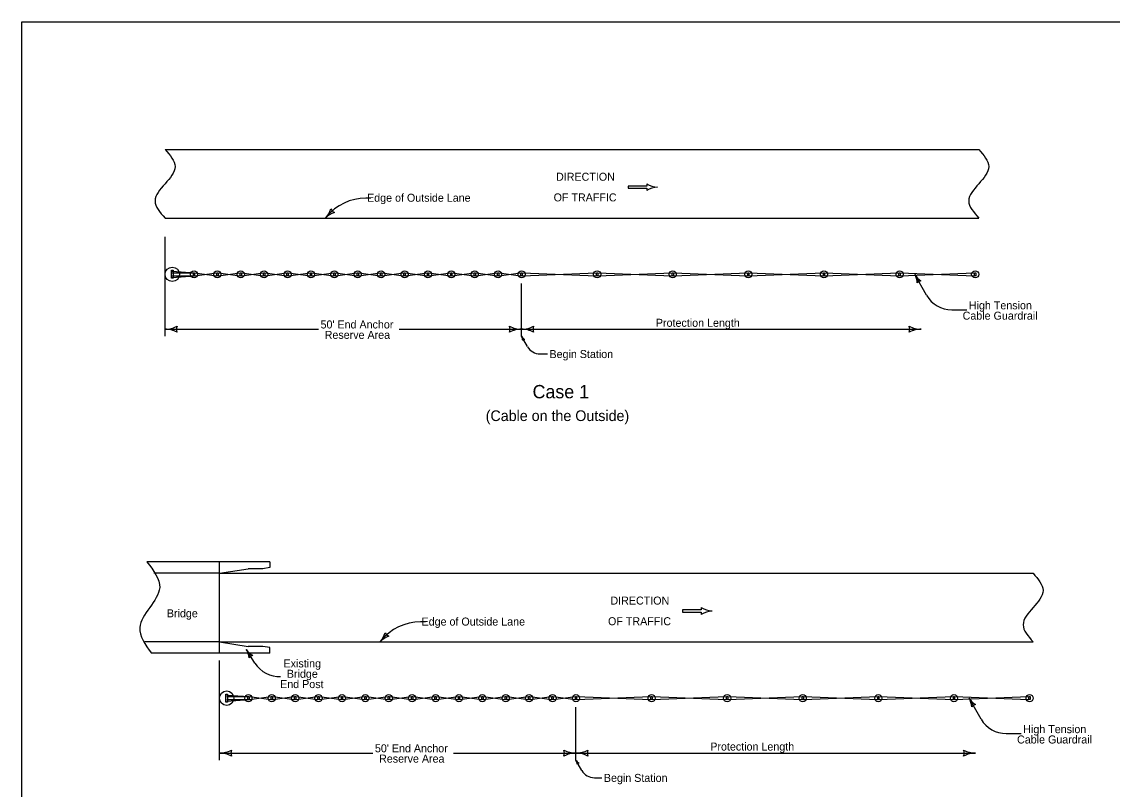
# Model space of a CAD drawing. Extents: x 10133 to 81668, y 7924 to 11018.
# Drawn here: x 20933 to 22568, y 8793 to 9944 of the extents above; entities that cross this region are included whole.
import ezdxf

# ---------------------------------------------------------------- set-up
doc = ezdxf.new("R2010")
doc.units = 0
for name, color, linetype in [('Default', 7, 'Continuous'), ('dsnCellElements', 7, 'Continuous'), ('DsnShtRevisedText', 7, 'Continuous'), ('dsnStdDimension', 7, 'Continuous'), ('Level 8', 7, 'Continuous'), ('SheetBorder', 7, 'Continuous')]:
    doc.layers.add(name, color=color, linetype=linetype)

msp = doc.modelspace()

# ---------------------------------------------------------------- linework, layer by layer
at = {"layer": 'Default'}
for p, q in [((21229, 9133.8), (21120.1, 9133.8)), ((21229, 8996.7), (21229, 9133.8)), ((21229, 9116.7), (21130.7, 9116.7)), ((21229, 9013.8), (21117.2, 9013.8)), ((21229, 8996.7), (21127, 8996.7))]:
    msp.add_line(p, q, dxfattribs=at)
msp.add_spline([(21120.1, 9133.8), (21139.3, 9095.3), (21124.3, 9065.3), (21109.3, 9035.3), (21127, 8996.7)], degree=3, dxfattribs=at)
at = {"layer": 'dsnCellElements'}
for p, q in [((21158.2, 9569.8), (21191.7, 9567.5)), ((21158.2, 9567.5), (21189.8, 9567.5)), ((21158.2, 9563), (21189.8, 9563)), ((21158.2, 9560.6), (21191.7, 9563)), ((21191.7, 9567.5), (21224.9, 9563)), ((21191.7, 9563), (21224.9, 9567.5)), ((21226.8, 9567.5), (21260, 9563)), ((21226.8, 9563), (21260, 9567.5)), ((21261.9, 9567.5), (21295.1, 9563)), ((21261.9, 9563), (21295.1, 9567.5)), ((21297, 9567.5), (21330.2, 9563)), ((21297, 9563), (21330.2, 9567.5)), ((21332.1, 9567.5), (21365.3, 9563)), ((21332.1, 9563), (21365.3, 9567.5)), ((21367.2, 9567.5), (21400.4, 9563)), ((21367.2, 9563), (21400.4, 9567.5)), ((21402.3, 9563), (21435.5, 9567.5)), ((21402.3, 9567.5), (21435.5, 9563)), ((21437.3, 9567.5), (21470.6, 9563)), ((21437.3, 9563), (21470.6, 9567.5)), ((21472.5, 9567.5), (21505.6, 9563)), ((21472.5, 9563), (21505.6, 9567.5)), ((21507.5, 9567.5), (21540.8, 9563)), ((21507.5, 9563), (21540.8, 9567.5)), ((21542.7, 9567.5), (21575.8, 9563)), ((21542.7, 9563), (21575.8, 9567.5)), ((21577.7, 9567.5), (21611, 9563)), ((21577.7, 9563), (21611, 9567.5)), ((21612.8, 9567.5), (21646, 9563)), ((21612.8, 9563), (21646, 9567.5)), ((21647.9, 9567.5), (21681.1, 9563)), ((21647.9, 9563), (21681.1, 9567.5)), ((21683, 9567.5), (21794.5, 9563)), ((21683, 9563), (21794.5, 9567.5)), ((21796.4, 9567.5), (21907.9, 9563)), ((21796.4, 9563), (21907.9, 9567.5)), ((21909.8, 9567.5), (22021.3, 9563)), ((21909.8, 9563), (22021.3, 9567.5)), ((22023.2, 9567.5), (22134.8, 9563)), ((22023.2, 9563), (22134.8, 9567.5)), ((22136.6, 9567.5), (22248.2, 9563)), ((22136.6, 9563), (22248.2, 9567.5)), ((22250, 9567.5), (22361.6, 9563)), ((22250, 9563), (22361.6, 9567.5)), ((21304.6, 9133.8), (21229, 9133.8)), ((21304.6, 9133.8), (21304.6, 9125.3)), ((21229, 9116.7), (21272.2, 9123.5)), ((21293.8, 9123.5), (21272.2, 9123.5)), ((21304.6, 9125.3), (21293.8, 9123.5)), ((21229, 8996.7), (21229, 9013.8)), ((21229, 9013.8), (21272.2, 9007.1)), ((21304.6, 8996.7), (21229, 8996.7)), ((21293.8, 9007.1), (21272.2, 9007.1)), ((21304.6, 9005.3), (21293.8, 9007.1)), ((21304.6, 8996.7), (21304.6, 9005.3)), ((21239.8, 8934.1), (21273.3, 8931.7)), ((21239.8, 8931.7), (21271.5, 8931.7)), ((21273.3, 8931.7), (21306.5, 8927.2)), ((21273.3, 8927.2), (21306.5, 8931.7)), ((21308.4, 8931.7), (21341.6, 8927.2)), ((21308.4, 8927.2), (21341.6, 8931.7)), ((21343.5, 8931.7), (21376.7, 8927.2)), ((21343.5, 8927.2), (21376.7, 8931.7)), ((21378.6, 8931.7), (21411.8, 8927.2)), ((21378.6, 8927.2), (21411.8, 8931.7)), ((21413.7, 8931.7), (21446.9, 8927.2)), ((21413.7, 8927.2), (21446.9, 8931.7)), ((21448.8, 8931.7), (21482, 8927.2)), ((21448.8, 8927.2), (21482, 8931.7)), ((21483.9, 8927.2), (21517.1, 8931.7)), ((21483.9, 8931.7), (21517.1, 8927.2)), ((21519, 8931.7), (21552.2, 8927.2)), ((21519, 8927.2), (21552.2, 8931.7)), ((21554.1, 8931.7), (21587.3, 8927.2)), ((21554.1, 8927.2), (21587.3, 8931.7)), ((21589.1, 8931.7), (21622.4, 8927.2)), ((21589.1, 8927.2), (21622.4, 8931.7)), ((21624.3, 8931.7), (21657.4, 8927.2)), ((21624.3, 8927.2), (21657.4, 8931.7)), ((21659.3, 8931.7), (21692.6, 8927.2)), ((21659.3, 8927.2), (21692.6, 8931.7)), ((21694.5, 8931.7), (21727.6, 8927.2)), ((21694.5, 8927.2), (21727.6, 8931.7)), ((21729.5, 8931.7), (21762.8, 8927.2)), ((21729.5, 8927.2), (21762.8, 8931.7)), ((21764.6, 8931.7), (21876.2, 8927.2)), ((21764.6, 8927.2), (21876.2, 8931.7)), ((21878, 8931.7), (21989.6, 8927.2)), ((21878, 8927.2), (21989.6, 8931.7)), ((21991.4, 8931.7), (22103, 8927.2)), ((21991.4, 8927.2), (22103, 8931.7)), ((22104.8, 8931.7), (22216.4, 8927.2)), ((22104.8, 8927.2), (22216.4, 8931.7)), ((22218.2, 8931.7), (22329.8, 8927.2)), ((22218.2, 8927.2), (22329.8, 8931.7)), ((22331.6, 8931.7), (22443.2, 8927.2)), ((22331.6, 8927.2), (22443.2, 8931.7)), ((21239.8, 8927.2), (21271.5, 8927.2)), ((21239.8, 8924.8), (21273.3, 8927.2))]:
    msp.add_line(p, q, dxfattribs=at)
for points in [[(21157, 9559.2), (21157, 9571.2), (21159.4, 9571.2), (21159.4, 9559.2)], [(21189.8, 9563), (21189.8, 9567.5), (21191.7, 9567.5), (21191.7, 9563)], [(21224.9, 9563), (21224.9, 9567.5), (21226.8, 9567.5), (21226.8, 9563)], [(21260, 9563), (21260, 9567.5), (21261.9, 9567.5), (21261.9, 9563)], [(21295.1, 9563), (21295.1, 9567.5), (21297, 9567.5), (21297, 9563)], [(21330.2, 9563), (21330.2, 9567.5), (21332.1, 9567.5), (21332.1, 9563)], [(21365.3, 9563), (21365.3, 9567.5), (21367.2, 9567.5), (21367.2, 9563)], [(21400.4, 9563), (21400.4, 9567.5), (21402.3, 9567.5), (21402.3, 9563)], [(21435.5, 9563), (21435.5, 9567.5), (21437.3, 9567.5), (21437.3, 9563)], [(21470.6, 9563), (21470.6, 9567.5), (21472.5, 9567.5), (21472.5, 9563)], [(21505.6, 9563), (21505.6, 9567.5), (21507.5, 9567.5), (21507.5, 9563)], [(21540.8, 9563), (21540.8, 9567.5), (21542.7, 9567.5), (21542.7, 9563)], [(21575.8, 9563), (21575.8, 9567.5), (21577.7, 9567.5), (21577.7, 9563)], [(21611, 9563), (21611, 9567.5), (21612.8, 9567.5), (21612.8, 9563)], [(21646, 9563), (21646, 9567.5), (21647.9, 9567.5), (21647.9, 9563)], [(21681.1, 9563), (21681.1, 9567.5), (21683, 9567.5), (21683, 9563)], [(21681.1, 9563), (21681.1, 9567.5), (21683, 9567.5), (21683, 9563)], [(21794.5, 9563), (21794.5, 9567.5), (21796.4, 9567.5), (21796.4, 9563)], [(21794.5, 9563), (21794.5, 9567.5), (21796.4, 9567.5), (21796.4, 9563)], [(21907.9, 9563), (21907.9, 9567.5), (21909.8, 9567.5), (21909.8, 9563)], [(21907.9, 9563), (21907.9, 9567.5), (21909.8, 9567.5), (21909.8, 9563)], [(22021.3, 9563), (22021.3, 9567.5), (22023.2, 9567.5), (22023.2, 9563)], [(22021.3, 9563), (22021.3, 9567.5), (22023.2, 9567.5), (22023.2, 9563)], [(22134.8, 9563), (22134.8, 9567.5), (22136.6, 9567.5), (22136.6, 9563)], [(22134.8, 9563), (22134.8, 9567.5), (22136.6, 9567.5), (22136.6, 9563)], [(22248.2, 9563), (22248.2, 9567.5), (22250, 9567.5), (22250, 9563)], [(22248.2, 9563), (22248.2, 9567.5), (22250, 9567.5), (22250, 9563)], [(22361.6, 9563), (22361.6, 9567.5), (22363.4, 9567.5), (22363.4, 9563)], [(21238.6, 8923.4), (21238.6, 8935.4), (21241, 8935.4), (21241, 8923.4)], [(21271.4, 8927.2), (21271.4, 8931.7), (21273.3, 8931.7), (21273.3, 8927.2)], [(21306.5, 8927.2), (21306.5, 8931.7), (21308.4, 8931.7), (21308.4, 8927.2)], [(21341.7, 8927.2), (21341.7, 8931.7), (21343.5, 8931.7), (21343.5, 8927.2)], [(21376.7, 8927.2), (21376.7, 8931.7), (21378.6, 8931.7), (21378.6, 8927.2)], [(21411.9, 8927.2), (21411.9, 8931.7), (21413.7, 8931.7), (21413.7, 8927.2)], [(21446.9, 8927.2), (21446.9, 8931.7), (21448.8, 8931.7), (21448.8, 8927.2)], [(21482, 8927.2), (21482, 8931.7), (21483.9, 8931.7), (21483.9, 8927.2)], [(21517.1, 8927.2), (21517.1, 8931.7), (21519, 8931.7), (21519, 8927.2)], [(21552.2, 8927.2), (21552.2, 8931.7), (21554.1, 8931.7), (21554.1, 8927.2)], [(21587.3, 8927.2), (21587.3, 8931.7), (21589.1, 8931.7), (21589.1, 8927.2)], [(21622.4, 8927.2), (21622.4, 8931.7), (21624.3, 8931.7), (21624.3, 8927.2)], [(21657.4, 8927.2), (21657.4, 8931.7), (21659.3, 8931.7), (21659.3, 8927.2)], [(21692.6, 8927.2), (21692.6, 8931.7), (21694.5, 8931.7), (21694.5, 8927.2)], [(21727.6, 8927.2), (21727.6, 8931.7), (21729.5, 8931.7), (21729.5, 8927.2)], [(21762.8, 8927.2), (21762.8, 8931.7), (21764.6, 8931.7), (21764.6, 8927.2)], [(21762.8, 8927.2), (21762.8, 8931.7), (21764.6, 8931.7), (21764.6, 8927.2)], [(21876.2, 8927.2), (21876.2, 8931.7), (21878, 8931.7), (21878, 8927.2)], [(21876.2, 8927.2), (21876.2, 8931.7), (21878, 8931.7), (21878, 8927.2)], [(21989.6, 8927.2), (21989.6, 8931.7), (21991.4, 8931.7), (21991.4, 8927.2)], [(21989.6, 8927.2), (21989.6, 8931.7), (21991.4, 8931.7), (21991.4, 8927.2)], [(22103, 8927.2), (22103, 8931.7), (22104.8, 8931.7), (22104.8, 8927.2)], [(22103, 8927.2), (22103, 8931.7), (22104.8, 8931.7), (22104.8, 8927.2)], [(22216.4, 8927.2), (22216.4, 8931.7), (22218.2, 8931.7), (22218.2, 8927.2)], [(22216.4, 8927.2), (22216.4, 8931.7), (22218.2, 8931.7), (22218.2, 8927.2)], [(22329.8, 8927.2), (22329.8, 8931.7), (22331.6, 8931.7), (22331.6, 8927.2)], [(22329.8, 8927.2), (22329.8, 8931.7), (22331.6, 8931.7), (22331.6, 8927.2)], [(22443.2, 8927.2), (22443.2, 8931.7), (22445, 8931.7), (22445, 8927.2)]]:
    msp.add_lwpolyline(points, close=True, dxfattribs=at)
for centre, radius in [((21158.2, 9565.2), 10.8), ((21190.8, 9565.2), 5.32), ((21225.8, 9565.2), 5.32), ((21261, 9565.2), 5.32), ((21296, 9565.2), 5.32), ((21331.2, 9565.2), 5.32), ((21366.2, 9565.2), 5.32), ((21401.4, 9565.2), 5.32), ((21436.4, 9565.2), 5.32), ((21471.5, 9565.2), 5.32), ((21506.6, 9565.2), 5.32), ((21541.7, 9565.2), 5.32), ((21576.8, 9565.2), 5.32), ((21611.9, 9565.2), 5.32), ((21646.9, 9565.2), 5.32), ((21682.1, 9565.2), 5.32), ((21682.1, 9565.2), 5.32), ((21795.5, 9565.2), 5.32), ((21795.5, 9565.2), 5.32), ((21908.9, 9565.2), 5.32), ((21908.9, 9565.2), 5.32), ((22022.3, 9565.2), 5.32), ((22022.3, 9565.2), 5.32), ((22135.7, 9565.2), 5.32), ((22135.7, 9565.2), 5.32), ((22249.1, 9565.2), 5.32), ((22249.1, 9565.2), 5.32), ((22362.5, 9565.2), 5.32), ((21239.8, 8929.4), 10.8), ((21272.4, 8929.4), 5.32), ((21307.4, 8929.4), 5.32), ((21342.6, 8929.4), 5.32), ((21377.6, 8929.4), 5.32), ((21412.8, 8929.4), 5.32), ((21447.8, 8929.4), 5.32), ((21483, 8929.4), 5.32), ((21518, 8929.4), 5.32), ((21553.2, 8929.4), 5.32), ((21588.2, 8929.4), 5.32), ((21623.3, 8929.4), 5.32), ((21658.4, 8929.4), 5.32), ((21693.5, 8929.4), 5.32), ((21728.6, 8929.4), 5.32), ((21763.7, 8929.4), 5.32), ((21763.7, 8929.4), 5.32), ((21877.1, 8929.4), 5.32), ((21877.1, 8929.4), 5.32), ((21990.5, 8929.4), 5.32), ((21990.5, 8929.4), 5.32), ((22103.9, 8929.4), 5.32), ((22103.9, 8929.4), 5.32), ((22217.3, 8929.4), 5.32), ((22217.3, 8929.4), 5.32), ((22330.7, 8929.4), 5.32), ((22330.7, 8929.4), 5.32), ((22444.1, 8929.4), 5.32)]:
    msp.add_circle(centre, radius, dxfattribs=at)
at = {"layer": 'DsnShtRevisedText'}
for p, q in [((21869.9, 9701), (21869.9, 9697.4)), ((21869.9, 9697.4), (21842, 9697.4)), ((21842, 9697.4), (21842, 9694.4)), ((21842, 9694.4), (21869.9, 9694.4)), ((21869.9, 9694.4), (21869.9, 9690.8)), ((21886.1, 9695.9), (21886.1, 9695.9)), ((21456.2, 9679.5), (21448.7, 9679.5)), ((21147.3, 9472.3), (21147.3, 9621.7)), ((21682.1, 9472.3), (21682.1, 9551.6)), ((22289.7, 9533.7), (22272, 9565)), ((22327.3, 9512), (22349.8, 9512)), ((21147.3, 9482.8), (21377.5, 9482.8)), ((21498.5, 9482.8), (21725, 9482.8)), ((21691, 9456.7), (21682.1, 9472.3)), ((21725, 9482.8), (21893, 9482.8)), ((21893, 9482.8), (22281.6, 9482.8)), ((21709.8, 9445.9), (21721, 9445.9)), ((21951.5, 9061.7), (21923.6, 9061.7)), ((21923.6, 9061.7), (21923.6, 9058.6)), ((21951.5, 9065.2), (21951.5, 9061.7)), ((21923.6, 9058.6), (21951.5, 9058.6)), ((21951.5, 9058.6), (21951.5, 9055.1)), ((21967.7, 9060.1), (21967.7, 9060.1)), ((21537.8, 9043.7), (21530.4, 9043.7)), ((21282.2, 8981.9), (21269.3, 9002.6)), ((21229, 8836.5), (21229, 8986)), ((21763.7, 8836.5), (21763.7, 8915.8)), ((22371.4, 8897.9), (22353.6, 8929.2)), ((22409, 8876.3), (22431.5, 8876.3)), ((21229, 8847.1), (21459.1, 8847.1)), ((21580.1, 8847.1), (21806.6, 8847.1)), ((21772.6, 8820.9), (21763.7, 8836.5)), ((21806.6, 8847.1), (21974.6, 8847.1)), ((21974.6, 8847.1), (22363.2, 8847.1)), ((21791.4, 8810.1), (21802.6, 8810.1))]:
    msp.add_line(p, q, dxfattribs=at)
for centre, radius, start, end in [((21887.4, 9728.6), 32.7, 237.618, 267.648), ((21887.4, 9663.2), 32.7, 92.352, 122.382), ((21448.7, 9603.3), 76.2, 90, 140.9894), ((21364.5, 9671.7), 32.4, 317.0027, 345.0752), ((21411.9, 9627.5), 32.4, 108.9302, 137.0027), ((21406.7, 9669.5), 12.5, 209.2694, 244.7361), ((22248.5, 9551.3), 27.2, 2.1589, 30.2314), ((22295.5, 9578.6), 27.2, 210.2314, 238.3038), ((22283.5, 9545.2), 10.5, 102.498, 137.9647), ((22327.3, 9555.6), 43.5, 210.2243, 270), ((21147.3, 9521.1), 38.3, 270, 298.0725), ((21179.4, 9482.8), 14.8, 162.2666, 197.7334), ((21650, 9482.8), 14.8, 342.2666, 17.7333), ((21682.1, 9521.1), 38.3, 241.9275, 270), ((21682.1, 9521.1), 38.3, 270, 298.0725), ((21714.2, 9482.8), 14.8, 162.2666, 197.7334), ((22249.5, 9482.8), 14.8, 342.2666, 17.7333), ((22281.6, 9521.1), 38.3, 241.9275, 270), ((21147.3, 9444.6), 38.3, 61.9275, 90), ((21682.1, 9444.6), 38.3, 90, 118.0725), ((21682.1, 9444.6), 38.3, 61.9275, 90), ((21670.3, 9465.5), 13.6, 2.1589, 30.2314), ((21693.8, 9479.2), 13.6, 210.2314, 238.3038), ((22281.6, 9444.6), 38.3, 90, 118.0725), ((21687.8, 9462.5), 5.25, 102.498, 137.9647), ((21709.8, 9467.6), 21.8, 210.2243, 270), ((21969.1, 9092.9), 32.7, 237.618, 267.648), ((21969.1, 9027.4), 32.7, 92.352, 122.382), ((21530.4, 8967.5), 76.2, 90, 140.9894), ((21446.2, 9035.9), 32.4, 317.0027, 345.0752), ((21493.5, 8991.8), 32.4, 108.9302, 137.0027), ((21488.3, 9033.7), 12.5, 209.2694, 244.7361), ((21246.3, 8988), 27.2, 4.5066, 32.5791), ((21292.2, 9017.3), 27.2, 212.5791, 240.6516), ((21281.5, 8983.4), 10.5, 104.8458, 140.3125), ((21318.9, 9005.3), 43.5, 212.5721, 272.3478), ((22330.1, 8915.5), 27.2, 2.1589, 30.2314), ((22377.1, 8942.9), 27.2, 210.2314, 238.3038), ((22365.1, 8909.5), 10.5, 102.498, 137.9647), ((22409, 8919.8), 43.5, 210.2243, 270), ((21229, 8885.3), 38.3, 270, 298.0725), ((21261, 8847.1), 14.8, 162.2666, 197.7334), ((21731.6, 8847.1), 14.8, 342.2666, 17.7333), ((21763.7, 8885.3), 38.3, 241.9275, 270), ((21763.7, 8885.3), 38.3, 270, 298.0725), ((21795.8, 8847.1), 14.8, 162.2666, 197.7334), ((22331.1, 8847.1), 14.8, 342.2666, 17.7333), ((22363.2, 8885.3), 38.3, 241.9275, 270), ((21229, 8808.8), 38.3, 61.9275, 90), ((21763.7, 8808.8), 38.3, 90, 118.0725), ((21763.7, 8808.8), 38.3, 61.9275, 90), ((21751.9, 8829.7), 13.6, 2.1589, 30.2314), ((21775.4, 8843.4), 13.6, 210.2314, 238.3038), ((21769.4, 8826.7), 5.25, 102.498, 137.9647), ((22363.2, 8808.8), 38.3, 90, 118.0725), ((21791.4, 8831.9), 21.8, 210.2243, 270)]:
    msp.add_arc(centre, radius, start, end, dxfattribs=at)
at = {"layer": 'dsnStdDimension'}
for p, q in [((21147.3, 9752.5), (22367.8, 9752.5)), ((21147.3, 9649.6), (22367.8, 9649.6)), ((21229, 9116.7), (22449.4, 9116.7)), ((21229, 9013.8), (22449.4, 9013.8))]:
    msp.add_line(p, q, dxfattribs=at)
for points in [[(21147.3, 9752.5), (21162.3, 9726.8), (21147.3, 9701), (21132.3, 9675.3), (21147.3, 9649.6)], [(22367.8, 9752.5), (22382.8, 9726.8), (22367.8, 9701), (22352.8, 9675.3), (22367.8, 9649.6)], [(22449.4, 9116.7), (22464.4, 9091), (22449.4, 9065.3), (22434.4, 9039.6), (22449.4, 9013.8)]]:
    msp.add_spline(points, degree=3, dxfattribs=at)
at = {"layer": 'SheetBorder'}
msp.add_lwpolyline([(20932.5, 9944), (24067.5, 9944), (24067.5, 7924), (20932.5, 7924)], close=True, dxfattribs=at)

# ---------------------------------------------------------------- texts
at = {"layer": 'DsnShtRevisedText'}
for s, p in [('DIRECTION', (21733.8, 9705.6)), ('Edge of Outside Lane', (21450.4, 9674.1)), ('OF TRAFFIC', (21730.2, 9674.6)), ('High Tension', (22353, 9512.7)), ('Cable Guardrail', (22343.7, 9497.2)), ("50' End Anchor", (21380.6, 9484)), ('Protection Length', (21883.6, 9486.5)), ('Reserve Area', (21386.8, 9468.4)), ('Begin Station', (21724, 9439.6)), ('DIRECTION', (21815.4, 9069.8)), ('Bridge', (21150.1, 9050.7)), ('Edge of Outside Lane', (21532.1, 9038.3)), ('OF TRAFFIC', (21811.8, 9038.8)), ('Existing', (21325.1, 8975.5)), ('Bridge', (21330.1, 8960)), ('End Post', (21320, 8944.5)), ('High Tension', (22434.6, 8876.9)), ('Cable Guardrail', (22425.3, 8861.4)), ("50' End Anchor", (21462.2, 8848.2)), ('Protection Length', (21965.2, 8850.8)), ('Reserve Area', (21468.4, 8832.7)), ('Begin Station', (21805.6, 8803.8))]:
    msp.add_text(s, height=12, dxfattribs=at).set_placement(p)
at = {"layer": 'Level 8'}
for s, height, p in [('Case 1', 20, (21698.6, 9379.2)), ('(Cable on the Outside)', 16, (21628.3, 9345.1))]:
    msp.add_text(s, height=height, dxfattribs=at).set_placement(p)

doc.saveas('drawing.dxf')
